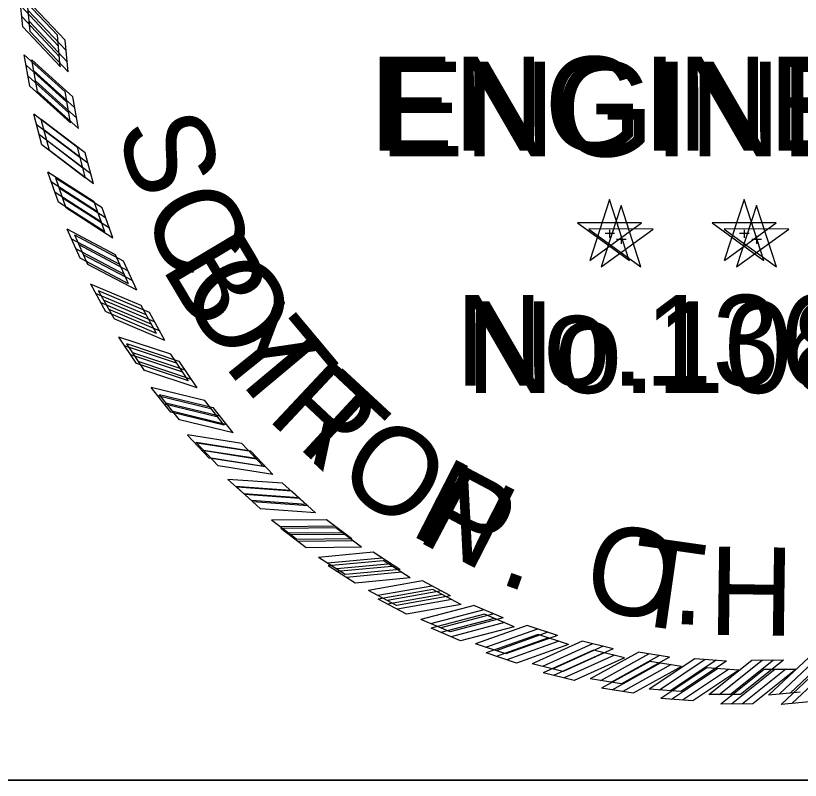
# Model space of a CAD drawing. Extents: x 0 to 1228740, y 0 to 152440.
# Drawn here: x 30.795 to 32.131, y 17.405 to 18.707 of the extents above; entities that cross this region are included whole.
import ezdxf

# ---------------------------------------------------------------- set-up
doc = ezdxf.new("R2010")
doc.units = 0
for name, color, linetype in [('R_No Plot', 7, 'Continuous'), ('STAMP_Byron', 7, 'Continuous'), ('STAMP_PP', 7, 'Continuous')]:
    doc.layers.add(name, color=color, linetype=linetype)

msp = doc.modelspace()

# ---------------------------------------------------------------- linework, layer by layer
at = {"layer": 'R_No Plot'}
for points in [[(30.6665, 20.1432), (30.6665, 17.4052), (33.4231, 17.4052)], [(33.4231, 17.4052), (30.6665, 17.4052), (30.6665, 20.1432)]]:
    msp.add_lwpolyline(points, dxfattribs=at)
at = {"layer": 'STAMP_Byron'}
for p, q in [((30.8065, 18.6885), (30.8015, 18.7423)), ((30.8065, 18.6885), (30.8015, 18.7423)), ((30.8705, 18.6204), (30.8655, 18.6743)), ((30.8705, 18.6204), (30.8655, 18.6743)), ((30.8186, 18.5874), (30.8092, 18.6406)), ((30.8186, 18.5874), (30.8092, 18.6406)), ((30.888, 18.5247), (30.8786, 18.5781)), ((30.888, 18.5247), (30.8786, 18.5781)), ((30.839, 18.4876), (30.8252, 18.5398)), ((30.839, 18.4876), (30.8252, 18.5398)), ((30.9133, 18.4309), (30.8996, 18.4833)), ((30.9133, 18.4309), (30.8996, 18.4833)), ((30.8675, 18.3898), (30.8495, 18.4407)), ((30.8675, 18.3898), (30.8495, 18.4407)), ((30.9463, 18.3394), (30.9283, 18.3905)), ((30.9463, 18.3394), (30.9283, 18.3905)), ((31.806, 18.3942), (31.7721, 18.2904)), ((31.806, 18.3942), (31.7721, 18.2904)), ((31.8396, 18.2905), (31.806, 18.3943)), ((31.8396, 18.2905), (31.806, 18.3943)), ((32.0352, 18.3942), (32.0014, 18.2904)), ((32.0352, 18.3942), (32.0014, 18.2904)), ((32.0689, 18.2905), (32.0352, 18.3943)), ((32.0689, 18.2905), (32.0352, 18.3943)), ((31.8605, 18.3546), (31.7514, 18.3547)), ((31.8605, 18.3546), (31.7514, 18.3547)), ((31.7515, 18.3546), (31.8397, 18.2904)), ((31.7515, 18.3546), (31.8397, 18.2904)), ((31.7723, 18.2905), (31.8606, 18.3545)), ((31.7723, 18.2905), (31.8606, 18.3545)), ((32.0897, 18.3546), (31.9806, 18.3547)), ((32.0897, 18.3546), (31.9806, 18.3547)), ((31.9807, 18.3546), (32.0689, 18.2904)), ((31.9807, 18.3546), (32.0689, 18.2904)), ((32.0015, 18.2905), (32.0898, 18.3545)), ((32.0015, 18.2905), (32.0898, 18.3545)), ((30.9041, 18.2947), (30.8819, 18.344)), ((30.9041, 18.2947), (30.8819, 18.344)), ((31.7982, 18.3371), (31.8144, 18.3371)), ((31.7982, 18.3371), (31.8144, 18.3371)), ((31.8061, 18.343), (31.8061, 18.3293)), ((31.8061, 18.343), (31.8061, 18.3293)), ((32.0274, 18.3371), (32.0436, 18.3371)), ((32.0274, 18.3371), (32.0436, 18.3371)), ((32.0353, 18.343), (32.0353, 18.3293)), ((32.0353, 18.343), (32.0353, 18.3293)), ((30.9868, 18.251), (30.9645, 18.3004)), ((30.9868, 18.251), (30.9645, 18.3004)), ((30.9483, 18.203), (30.9222, 18.2503)), ((30.9483, 18.203), (30.9222, 18.2503)), ((31.0344, 18.1663), (31.0081, 18.2137)), ((31.0344, 18.1663), (31.0081, 18.2137)), ((31, 18.1152), (30.9701, 18.1602)), ((31, 18.1152), (30.9701, 18.1602)), ((31.0888, 18.0857), (31.0587, 18.1308)), ((31.0888, 18.0857), (31.0587, 18.1308)), ((31.0588, 18.032), (31.0252, 18.0743)), ((31.0588, 18.032), (31.0252, 18.0743)), ((31.1497, 18.01), (31.116, 18.0524)), ((31.1497, 18.01), (31.116, 18.0524)), ((31.1242, 17.9539), (31.0873, 17.9933)), ((31.1242, 17.9539), (31.0873, 17.9933)), ((31.2166, 17.9395), (31.1796, 17.979)), ((31.2166, 17.9395), (31.1796, 17.979)), ((31.1959, 17.8815), (31.1558, 17.9178)), ((31.1959, 17.8815), (31.1558, 17.9178)), ((31.2892, 17.8747), (31.249, 17.9111)), ((31.2892, 17.8747), (31.249, 17.9111)), ((31.2733, 17.8153), (31.2304, 17.8481)), ((31.2733, 17.8153), (31.2304, 17.8481)), ((31.3668, 17.8162), (31.3238, 17.8491)), ((31.3668, 17.8162), (31.3238, 17.8491)), ((31.449, 17.7643), (31.4034, 17.7936)), ((31.449, 17.7643), (31.4034, 17.7936)), ((31.3559, 17.7557), (31.3104, 17.7848)), ((31.3559, 17.7557), (31.3104, 17.7848)), ((31.5352, 17.7194), (31.4874, 17.7448)), ((31.5352, 17.7194), (31.4874, 17.7448)), ((31.4431, 17.7031), (31.3954, 17.7284)), ((31.4431, 17.7031), (31.3954, 17.7284)), ((31.6248, 17.6818), (31.575, 17.7031)), ((31.6248, 17.6818), (31.575, 17.7031)), ((31.5344, 17.6579), (31.4847, 17.6791)), ((31.5344, 17.6579), (31.4847, 17.6791)), ((31.7173, 17.6516), (31.6659, 17.6687)), ((31.7173, 17.6516), (31.6659, 17.6687)), ((31.8119, 17.6292), (31.7592, 17.6421)), ((31.8119, 17.6292), (31.7592, 17.6421)), ((31.6291, 17.6204), (31.5779, 17.6374)), ((31.6291, 17.6204), (31.5779, 17.6374)), ((31.908, 17.6147), (31.8545, 17.6232)), ((31.908, 17.6147), (31.8545, 17.6232)), ((31.7266, 17.5908), (31.6741, 17.6036)), ((31.7266, 17.5908), (31.6741, 17.6036)), ((32.005, 17.6082), (31.951, 17.6122)), ((32.005, 17.6082), (31.951, 17.6122)), ((32.1022, 17.6097), (32.048, 17.6092)), ((32.1022, 17.6097), (32.048, 17.6092)), ((31.8262, 17.5694), (31.7728, 17.5778)), ((31.8262, 17.5694), (31.7728, 17.5778)), ((31.9272, 17.5563), (31.8733, 17.5602)), ((31.9272, 17.5563), (31.8733, 17.5602)), ((32.029, 17.5516), (31.975, 17.5511)), ((32.029, 17.5516), (31.975, 17.5511)), ((32.1308, 17.5552), (32.077, 17.5503)), ((32.1308, 17.5552), (32.077, 17.5503))]:
    msp.add_line(p, q, dxfattribs=at)
for points in [[(30.8655, 18.6742), (30.8015, 18.7424)], [(30.8655, 18.6742), (30.8015, 18.7424)], [(30.867, 18.6563), (30.803, 18.7244)], [(30.867, 18.6563), (30.803, 18.7244)], [(30.8691, 18.6376), (30.8051, 18.7058)], [(30.8691, 18.6376), (30.8051, 18.7058)], [(30.8706, 18.6203), (30.8065, 18.6885)], [(30.8706, 18.6203), (30.8065, 18.6885)], [(30.8786, 18.578), (30.8091, 18.6406)], [(30.8786, 18.578), (30.8091, 18.6406)], [(30.8815, 18.5603), (30.8121, 18.6229)], [(30.8815, 18.5603), (30.8121, 18.6229)], [(30.8852, 18.5418), (30.8158, 18.6045)], [(30.8852, 18.5418), (30.8158, 18.6045)], [(30.8881, 18.5247), (30.8186, 18.5873)], [(30.8881, 18.5247), (30.8186, 18.5873)], [(30.8995, 18.4832), (30.8252, 18.5399)], [(30.8995, 18.4832), (30.8252, 18.5399)], [(30.9039, 18.4658), (30.8296, 18.5224)], [(30.9039, 18.4658), (30.8296, 18.5224)], [(30.9091, 18.4477), (30.8348, 18.5044)], [(30.9091, 18.4477), (30.8348, 18.5044)], [(30.9134, 18.4308), (30.839, 18.4875)], [(30.9134, 18.4308), (30.839, 18.4875)], [(30.9283, 18.3904), (30.8495, 18.4408)], [(30.9283, 18.3904), (30.8495, 18.4408)], [(30.9341, 18.3734), (30.8553, 18.4238)], [(30.9341, 18.3734), (30.8553, 18.4238)], [(30.9407, 18.3559), (30.862, 18.4062)], [(30.9407, 18.3559), (30.862, 18.4062)], [(30.9464, 18.3394), (30.8676, 18.3897)], [(30.9464, 18.3394), (30.8676, 18.3897)], [(30.9645, 18.3004), (30.8819, 18.344)], [(30.9645, 18.3004), (30.8819, 18.344)], [(30.9718, 18.2839), (30.8891, 18.3275)], [(30.9718, 18.2839), (30.8891, 18.3275)], [(30.9798, 18.2669), (30.8972, 18.3106)], [(30.9798, 18.2669), (30.8972, 18.3106)], [(30.9868, 18.251), (30.9041, 18.2947)], [(30.9868, 18.251), (30.9041, 18.2947)], [(31.0081, 18.2136), (30.9221, 18.2503)], [(31.0081, 18.2136), (30.9221, 18.2503)], [(31.0167, 18.1978), (30.9307, 18.2345)], [(31.0167, 18.1978), (30.9307, 18.2345)], [(31.0262, 18.1815), (30.9401, 18.2182)], [(31.0262, 18.1815), (30.9401, 18.2182)], [(31.0344, 18.1662), (30.9484, 18.2029)], [(31.0344, 18.1662), (30.9484, 18.2029)], [(31.0588, 18.1307), (30.97, 18.1602)], [(31.0588, 18.1307), (30.97, 18.1602)], [(31.0686, 18.1157), (30.9799, 18.1451)], [(31.0686, 18.1157), (30.9799, 18.1451)], [(31.0794, 18.1003), (30.9906, 18.1297)], [(31.0794, 18.1003), (30.9906, 18.1297)], [(31.0889, 18.0857), (31.0001, 18.1152)], [(31.0889, 18.0857), (31.0001, 18.1152)], [(31.116, 18.0523), (31.0252, 18.0743)], [(31.116, 18.0523), (31.0252, 18.0743)], [(31.1271, 18.0381), (31.0362, 18.0601)], [(31.1271, 18.0381), (31.0362, 18.0601)], [(31.1391, 18.0237), (31.0482, 18.0457)], [(31.1391, 18.0237), (31.0482, 18.0457)], [(31.1498, 18.0099), (31.0589, 18.032)], [(31.1498, 18.0099), (31.0589, 18.032)], [(31.1796, 17.9789), (31.0872, 17.9934)], [(31.1796, 17.9789), (31.0872, 17.9934)], [(31.1918, 17.9657), (31.0994, 17.9801)], [(31.1918, 17.9657), (31.0994, 17.9801)], [(31.2049, 17.9523), (31.1126, 17.9667)], [(31.2049, 17.9523), (31.1126, 17.9667)], [(31.2167, 17.9395), (31.1243, 17.9539)], [(31.2167, 17.9395), (31.1243, 17.9539)], [(31.249, 17.911), (31.1558, 17.9178)], [(31.249, 17.911), (31.1558, 17.9178)], [(31.2623, 17.8988), (31.169, 17.9056)], [(31.2623, 17.8988), (31.169, 17.9056)], [(31.2765, 17.8865), (31.1832, 17.8933)], [(31.2765, 17.8865), (31.1832, 17.8933)], [(31.2893, 17.8747), (31.196, 17.8815)], [(31.2893, 17.8747), (31.196, 17.8815)], [(31.3238, 17.849), (31.2303, 17.8481)], [(31.3238, 17.849), (31.2303, 17.8481)], [(31.338, 17.838), (31.2445, 17.837)], [(31.338, 17.838), (31.2445, 17.837)], [(31.3532, 17.8269), (31.2597, 17.826)], [(31.3532, 17.8269), (31.2597, 17.826)], [(31.3669, 17.8162), (31.2734, 17.8153)], [(31.3669, 17.8162), (31.2734, 17.8153)], [(31.4034, 17.7935), (31.3103, 17.7848)], [(31.4034, 17.7935), (31.3103, 17.7848)], [(31.4185, 17.7836), (31.3254, 17.775)], [(31.4185, 17.7836), (31.3254, 17.775)], [(31.4345, 17.7739), (31.3414, 17.7652)], [(31.4345, 17.7739), (31.3414, 17.7652)], [(31.4491, 17.7644), (31.356, 17.7557)], [(31.4491, 17.7644), (31.356, 17.7557)], [(31.4874, 17.7447), (31.3953, 17.7284)], [(31.4874, 17.7447), (31.3953, 17.7284)], [(31.5032, 17.7361), (31.4112, 17.7198)], [(31.5032, 17.7361), (31.4112, 17.7198)], [(31.52, 17.7277), (31.4279, 17.7114)], [(31.52, 17.7277), (31.4279, 17.7114)], [(31.5353, 17.7194), (31.4432, 17.7031)], [(31.5353, 17.7194), (31.4432, 17.7031)], [(31.5751, 17.703), (31.4847, 17.6791)], [(31.5751, 17.703), (31.4847, 17.6791)], [(31.5916, 17.6958), (31.5012, 17.6719)], [(31.5916, 17.6958), (31.5012, 17.6719)], [(31.609, 17.6888), (31.5186, 17.6649)], [(31.609, 17.6888), (31.5186, 17.6649)], [(31.6249, 17.6818), (31.5345, 17.6579)], [(31.6249, 17.6818), (31.5345, 17.6579)], [(31.6659, 17.6687), (31.5778, 17.6374)], [(31.6659, 17.6687), (31.5778, 17.6374)], [(31.683, 17.6628), (31.5948, 17.6316)], [(31.683, 17.6628), (31.5948, 17.6316)], [(31.7009, 17.6573), (31.6128, 17.626)], [(31.7009, 17.6573), (31.6128, 17.626)], [(31.7174, 17.6517), (31.6292, 17.6204)], [(31.7174, 17.6517), (31.6292, 17.6204)], [(31.7593, 17.642), (31.6741, 17.6036)], [(31.7593, 17.642), (31.6741, 17.6036)], [(31.7768, 17.6376), (31.6915, 17.5991)], [(31.7768, 17.6376), (31.6915, 17.5991)], [(31.7951, 17.6335), (31.7098, 17.5951)], [(31.7951, 17.6335), (31.7098, 17.5951)], [(31.812, 17.6293), (31.7267, 17.5908)], [(31.812, 17.6293), (31.7267, 17.5908)], [(31.8546, 17.6231), (31.7728, 17.5778)], [(31.8546, 17.6231), (31.7728, 17.5778)], [(31.8723, 17.6201), (31.7905, 17.5748)], [(31.8723, 17.6201), (31.7905, 17.5748)], [(31.8909, 17.6176), (31.8091, 17.5723)], [(31.8909, 17.6176), (31.8091, 17.5723)], [(31.9081, 17.6148), (31.8263, 17.5694)], [(31.9081, 17.6148), (31.8263, 17.5694)], [(32.1451, 17.6143), (32.0769, 17.5502)], [(32.1451, 17.6143), (32.0769, 17.5502)], [(32.163, 17.6158), (32.0949, 17.5517)], [(32.163, 17.6158), (32.0949, 17.5517)], [(32.1817, 17.6179), (32.1135, 17.5539)], [(32.1817, 17.6179), (32.1135, 17.5539)], [(31.951, 17.6122), (31.8733, 17.5602)], [(31.951, 17.6122), (31.8733, 17.5602)], [(31.969, 17.6107), (31.8912, 17.5587)], [(31.969, 17.6107), (31.8912, 17.5587)], [(31.9877, 17.6097), (31.91, 17.5578)], [(31.9877, 17.6097), (31.91, 17.5578)], [(32.0051, 17.6083), (31.9273, 17.5563)], [(32.0051, 17.6083), (31.9273, 17.5563)], [(32.0481, 17.6092), (31.9749, 17.551)], [(32.0481, 17.6092), (31.9749, 17.551)], [(32.0661, 17.6092), (31.9929, 17.551)], [(32.0661, 17.6092), (31.9929, 17.551)], [(32.0849, 17.6098), (32.0117, 17.5516)], [(32.0849, 17.6098), (32.0117, 17.5516)], [(32.1023, 17.6098), (32.0291, 17.5516)], [(32.1023, 17.6098), (32.0291, 17.5516)]]:
    msp.add_lwpolyline(points, dxfattribs=at)
at = {"layer": 'STAMP_PP'}
for p, q in [((30.8192, 18.6803), (30.8142, 18.7345)), ((30.8837, 18.6117), (30.8787, 18.666)), ((30.8314, 18.5785), (30.822, 18.6321)), ((30.9013, 18.5154), (30.8918, 18.5691)), ((30.8519, 18.478), (30.8381, 18.5306)), ((30.9268, 18.4209), (30.9129, 18.4737)), ((30.8807, 18.3796), (30.8626, 18.4309)), ((30.96, 18.3289), (30.9419, 18.3803)), ((31.8255, 18.384), (31.7915, 18.2795)), ((31.8594, 18.2796), (31.8256, 18.3841)), ((32.0563, 18.384), (32.0222, 18.2795)), ((32.0902, 18.2796), (32.0564, 18.3841)), ((31.8804, 18.3441), (31.7705, 18.3442)), ((31.7706, 18.3441), (31.8594, 18.2795)), ((31.7916, 18.2796), (31.8805, 18.3441)), ((32.1112, 18.3441), (32.0013, 18.3442)), ((32.0014, 18.3441), (32.0902, 18.2795)), ((32.0224, 18.2796), (32.1113, 18.3441)), ((30.9175, 18.2838), (30.8952, 18.3335)), ((31.8177, 18.3266), (31.834, 18.3266)), ((31.8256, 18.3324), (31.8256, 18.3186)), ((32.0485, 18.3266), (32.0648, 18.3266)), ((32.0564, 18.3324), (32.0564, 18.3186)), ((31.0007, 18.2399), (30.9784, 18.2896)), ((30.9621, 18.1915), (30.9357, 18.2391)), ((31.0487, 18.1545), (31.0223, 18.2022)), ((31.0141, 18.1031), (30.9839, 18.1484)), ((31.1035, 18.0734), (31.0732, 18.1188)), ((31.0733, 18.0193), (31.0395, 18.062)), ((31.1648, 17.9971), (31.1309, 18.0399)), ((31.1392, 17.9407), (31.1019, 17.9804)), ((31.2322, 17.9262), (31.1949, 17.966)), ((31.2113, 17.8678), (31.1709, 17.9043)), ((31.3052, 17.861), (31.2648, 17.8976)), ((31.2892, 17.8012), (31.246, 17.8342)), ((31.3834, 17.8021), (31.34, 17.8352)), ((31.4661, 17.7499), (31.4202, 17.7793)), ((31.3724, 17.7411), (31.3266, 17.7705)), ((31.5529, 17.7046), (31.5047, 17.7301)), ((31.4602, 17.6882), (31.4121, 17.7136)), ((31.6432, 17.6667), (31.593, 17.6882)), ((31.5521, 17.6427), (31.5021, 17.6641)), ((31.7362, 17.6364), (31.6845, 17.6536)), ((31.8315, 17.6138), (31.7785, 17.6267)), ((31.6475, 17.6049), (31.5959, 17.6221)), ((31.9283, 17.5992), (31.8744, 17.6077)), ((31.7456, 17.5751), (31.6928, 17.588)), ((32.0259, 17.5927), (31.9715, 17.5967)), ((32.1238, 17.5942), (32.0692, 17.5937)), ((31.8459, 17.5536), (31.7922, 17.5621)), ((31.9476, 17.5404), (31.8934, 17.5444)), ((32.0501, 17.5356), (31.9957, 17.5351)), ((32.1526, 17.5393), (32.0984, 17.5343))]:
    msp.add_line(p, q, dxfattribs=at)
for points in [[(30.8787, 18.666), (30.8142, 18.7346)], [(30.8802, 18.6479), (30.8157, 18.7165)], [(30.8823, 18.6291), (30.8178, 18.6977)], [(30.8838, 18.6117), (30.8193, 18.6803)], [(30.8918, 18.5691), (30.8219, 18.6321)], [(30.8948, 18.5512), (30.8249, 18.6142)], [(30.8985, 18.5327), (30.8286, 18.5957)], [(30.9014, 18.5154), (30.8315, 18.5784)], [(30.9129, 18.4736), (30.838, 18.5307)], [(30.9174, 18.456), (30.8425, 18.5131)], [(30.9226, 18.4379), (30.8477, 18.4949)], [(30.9269, 18.4209), (30.852, 18.478)], [(30.9418, 18.3802), (30.8625, 18.4309)], [(30.9477, 18.3631), (30.8684, 18.4138)], [(30.9544, 18.3454), (30.8751, 18.3961)], [(30.9601, 18.3288), (30.8808, 18.3795)], [(30.9784, 18.2895), (30.8951, 18.3335)], [(30.9857, 18.2729), (30.9024, 18.3169)], [(30.9938, 18.2559), (30.9105, 18.2998)], [(31.0008, 18.2398), (30.9176, 18.2838)], [(31.0223, 18.2022), (30.9357, 18.2391)], [(31.0309, 18.1862), (30.9443, 18.2232)], [(31.0404, 18.1699), (30.9538, 18.2068)], [(31.0487, 18.1545), (30.9621, 18.1914)], [(31.0732, 18.1187), (30.9839, 18.1484)], [(31.0831, 18.1036), (30.9938, 18.1332)], [(31.094, 18.0881), (31.0046, 18.1177)], [(31.1035, 18.0734), (31.0142, 18.1031)], [(31.1309, 18.0398), (31.0394, 18.062)], [(31.142, 18.0255), (31.0505, 18.0477)], [(31.1541, 18.0109), (31.0626, 18.0331)], [(31.1649, 17.9971), (31.0734, 18.0193)], [(31.1949, 17.9659), (31.1019, 17.9804)], [(31.2072, 17.9526), (31.1142, 17.9671)], [(31.2204, 17.939), (31.1274, 17.9536)], [(31.2323, 17.9262), (31.1393, 17.9407)], [(31.2648, 17.8975), (31.1709, 17.9043)], [(31.2781, 17.8852), (31.1842, 17.8921)], [(31.2924, 17.8729), (31.1985, 17.8797)], [(31.3053, 17.861), (31.2114, 17.8678)], [(31.3401, 17.8351), (31.2459, 17.8342)], [(31.3544, 17.824), (31.2602, 17.8231)], [(31.3696, 17.8129), (31.2755, 17.8119)], [(31.3835, 17.8021), (31.2893, 17.8012)], [(31.4203, 17.7792), (31.3265, 17.7705)], [(31.4354, 17.7693), (31.3417, 17.7606)], [(31.4516, 17.7595), (31.3578, 17.7507)], [(31.4662, 17.7499), (31.3725, 17.7411)], [(31.5048, 17.7301), (31.4121, 17.7136)], [(31.5207, 17.7215), (31.428, 17.705)], [(31.5376, 17.713), (31.4449, 17.6965)], [(31.553, 17.7046), (31.4603, 17.6882)], [(31.5931, 17.6881), (31.5021, 17.6641)], [(31.6097, 17.6808), (31.5187, 17.6568)], [(31.6272, 17.6738), (31.5362, 17.6497)], [(31.6433, 17.6667), (31.5522, 17.6427)], [(31.6845, 17.6536), (31.5958, 17.6221)], [(31.7017, 17.6477), (31.613, 17.6162)], [(31.7197, 17.6421), (31.631, 17.6106)], [(31.7363, 17.6364), (31.6476, 17.6049)], [(31.7785, 17.6267), (31.6927, 17.588)], [(31.7961, 17.6222), (31.7103, 17.5835)], [(31.8146, 17.6182), (31.7288, 17.5795)], [(31.8315, 17.6139), (31.7457, 17.5752)], [(31.8744, 17.6077), (31.7921, 17.562)], [(31.8923, 17.6047), (31.81, 17.559)], [(31.9111, 17.6022), (31.8287, 17.5565)], [(32.185, 17.6003), (32.1164, 17.5358)], [(31.9283, 17.5993), (31.846, 17.5536)], [(31.9716, 17.5966), (31.8933, 17.5443)], [(31.9896, 17.5951), (31.9114, 17.5428)], [(32.0085, 17.5942), (31.9302, 17.5419)], [(32.026, 17.5927), (31.9477, 17.5404)], [(32.0693, 17.5937), (31.9956, 17.5351)], [(32.0874, 17.5937), (32.0137, 17.5351)], [(32.1063, 17.5943), (32.0326, 17.5357)], [(32.1238, 17.5943), (32.0501, 17.5357)], [(32.1669, 17.5988), (32.0983, 17.5343)]]:
    msp.add_lwpolyline(points, dxfattribs=at)

# ---------------------------------------------------------------- texts
at = {"layer": 'STAMP_Byron'}
for s, height, p in [('ENGINEER', 0.16046, (31.3969, 18.4773)), ('ENGINEER', 0.16046, (31.3969, 18.4773)), ('No.13640', 0.15472, (31.5436, 18.0772)), ('No.13640', 0.15472, (31.5436, 18.0772))]:
    msp.add_text(s, height=height, dxfattribs=at).set_placement(p)
for s, rotation, p in [('B', 300.7985, (31.0412, 18.2793)), ('B', 300.7985, (31.0412, 18.2793)), ('Y', 308.8241, (31.1215, 18.1447)), ('Y', 308.8241, (31.1215, 18.1447)), ('R', 316.8497, (31.2197, 18.0226)), ('R', 316.8497, (31.2197, 18.0226)), ('O', 324.8753, (31.334, 17.9155)), ('O', 324.8753, (31.334, 17.9155)), ('N', 332.9009, (31.4622, 17.8254)), ('N', 332.9009, (31.4622, 17.8254)), ('O', 349.3169, (31.7566, 17.701)), ('O', 349.3169, (31.7566, 17.701)), ('.', 357.3425, (31.9106, 17.672)), ('.', 357.3425, (31.9106, 17.672))]:
    msp.add_text(s, height=0.1493, rotation=rotation, dxfattribs=at).set_placement(p)
at = {"layer": 'STAMP_PP'}
for s, height, p in [('ENGINEER', 0.16155, (31.4137, 18.4677)), ('No.10887', 0.15578, (31.5614, 18.0649))]:
    msp.add_text(s, height=height, dxfattribs=at).set_placement(p)
for s, rotation, p in [('S', 286.9475, (30.9653, 18.5171)), ('C', 294.2435, (31.0071, 18.3799)), ('O', 301.9044, (31.0694, 18.2429)), ('T', 309.93, (31.1536, 18.1096)), ('T', 317.226, (31.2456, 17.9997)), ('P', 332.1828, (31.4737, 17.8153)), ('T', 351.882, (31.832, 17.6734)), ('H', 359.178, (31.974, 17.6531)), ('.', 340.2084, (31.6136, 17.7427))]:
    msp.add_text(s, height=0.1503, rotation=rotation, dxfattribs=at).set_placement(p)

doc.saveas('drawing.dxf')
